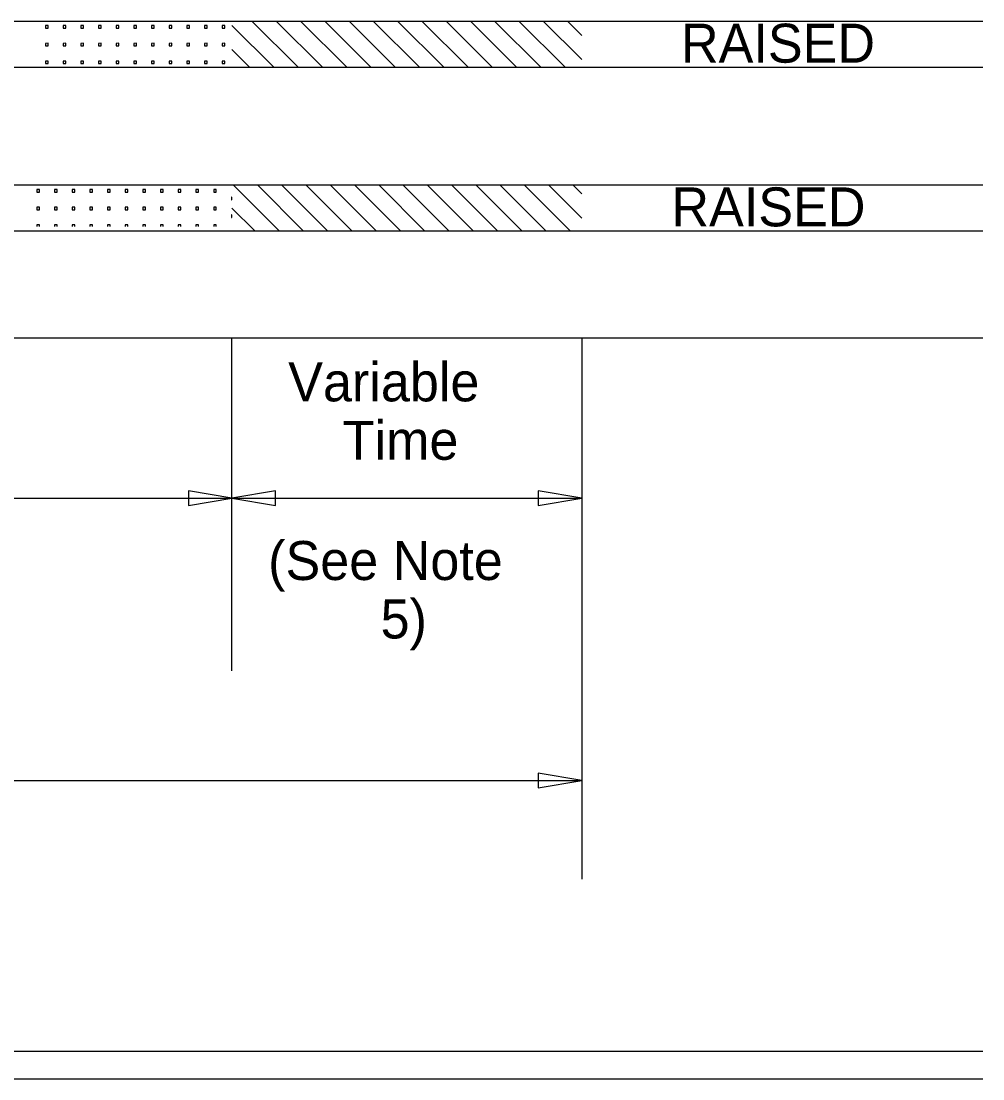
# Model space of a CAD drawing. Extents: x 15 to 764, y 7 to 487.
# Drawn here: x 670.2 to 756.6, y 29.1 to 124.1 of the extents above; entities that cross this region are included whole.
import ezdxf

# ---------------------------------------------------------------- set-up
doc = ezdxf.new("R2010")
doc.units = 0
for name, color, linetype in [('Default', 7, 'Continuous'), ('Dimension', 7, 'Continuous'), ('TextStructures', 7, 'Continuous')]:
    doc.layers.add(name, color=color, linetype=linetype)

msp = doc.modelspace()

# ---------------------------------------------------------------- linework, layer by layer
at = {"layer": 'Default'}
for p, q in [((462.687, 124.052), (756.61, 124.052)), ((706.225, 124.052), (710.375, 119.905)), ((708.406, 124.052), (712.555, 119.905)), ((710.586, 124.052), (714.736, 119.905)), ((712.766, 124.052), (716.916, 119.905)), ((714.947, 124.052), (719.097, 119.905)), ((717.127, 124.052), (720.584, 120.598)), ((719.308, 124.052), (720.584, 122.777)), ((462.687, 119.905), (756.61, 119.905)), ((462.687, 109.343), (756.61, 109.343)), ((708.887, 109.343), (713.014, 105.216)), ((711.066, 109.343), (715.194, 105.216)), ((713.246, 109.343), (717.374, 105.216)), ((715.426, 109.343), (719.553, 105.216)), ((717.606, 109.343), (720.584, 106.366)), ((719.786, 109.343), (720.584, 108.545)), ((462.687, 95.608), (756.61, 95.608)), ((689.177, 65.69), (689.177, 95.608)), ((720.584, 95.608), (720.584, 46.998)), ((624.556, 81.197), (689.177, 81.197)), ((689.177, 81.197), (720.584, 81.197)), ((495.877, 55.858), (720.584, 55.858))]:
    msp.add_line(p, q, dxfattribs=at)
for points in [[(672.656, 123.41), (672.656, 123.649), (672.417, 123.648), (672.417, 123.41), (672.656, 123.41)], [(672.656, 123.41), (672.656, 123.649), (672.417, 123.648), (672.417, 123.41), (672.656, 123.41)], [(674.242, 123.41), (674.242, 123.649), (674.003, 123.648), (674.003, 123.41), (674.242, 123.41)], [(674.242, 123.41), (674.242, 123.649), (674.003, 123.648), (674.003, 123.41), (674.242, 123.41)], [(675.832, 123.41), (675.832, 123.649), (675.593, 123.648), (675.593, 123.41), (675.832, 123.41)], [(675.832, 123.41), (675.832, 123.649), (675.593, 123.648), (675.593, 123.41), (675.832, 123.41)], [(677.418, 123.41), (677.418, 123.649), (677.179, 123.648), (677.179, 123.41), (677.418, 123.41)], [(677.418, 123.41), (677.418, 123.649), (677.179, 123.648), (677.179, 123.41), (677.418, 123.41)], [(679.008, 123.41), (679.008, 123.649), (678.769, 123.648), (678.769, 123.41), (679.008, 123.41)], [(679.008, 123.41), (679.008, 123.649), (678.769, 123.648), (678.769, 123.41), (679.008, 123.41)], [(680.594, 123.41), (680.594, 123.649), (680.355, 123.648), (680.355, 123.41), (680.594, 123.41)], [(680.594, 123.41), (680.594, 123.649), (680.355, 123.648), (680.355, 123.41), (680.594, 123.41)], [(682.184, 123.41), (682.184, 123.649), (681.945, 123.648), (681.945, 123.41), (682.184, 123.41)], [(682.184, 123.41), (682.184, 123.649), (681.945, 123.648), (681.945, 123.41), (682.184, 123.41)], [(683.77, 123.41), (683.77, 123.649), (683.532, 123.648), (683.532, 123.41), (683.77, 123.41)], [(683.77, 123.41), (683.77, 123.649), (683.532, 123.648), (683.532, 123.41), (683.77, 123.41)], [(685.36, 123.41), (685.36, 123.649), (685.121, 123.648), (685.121, 123.41), (685.36, 123.41)], [(685.36, 123.41), (685.36, 123.649), (685.121, 123.648), (685.121, 123.41), (685.36, 123.41)], [(686.947, 123.41), (686.947, 123.649), (686.708, 123.648), (686.708, 123.41), (686.947, 123.41)], [(686.947, 123.41), (686.947, 123.649), (686.708, 123.648), (686.708, 123.41), (686.947, 123.41)], [(688.536, 123.41), (688.536, 123.649), (688.297, 123.648), (688.297, 123.41), (688.536, 123.41)], [(688.536, 123.41), (688.536, 123.649), (688.297, 123.648), (688.297, 123.41), (688.536, 123.41)], [(689.177, 123.671), (692.943, 119.905)], [(690.973, 124.052), (695.121, 119.905)], [(693.153, 124.052), (697.301, 119.905)], [(695.33, 124.052), (699.48, 119.905)], [(697.508, 124.052), (701.658, 119.905)], [(699.687, 124.052), (703.835, 119.905)], [(701.867, 124.052), (706.015, 119.905)], [(704.045, 124.052), (708.195, 119.905)], [(672.656, 121.823), (672.656, 122.062), (672.417, 122.06), (672.417, 121.823), (672.656, 121.823)], [(672.656, 121.823), (672.656, 122.062), (672.417, 122.06), (672.417, 121.823), (672.656, 121.823)], [(674.242, 121.823), (674.242, 122.062), (674.003, 122.06), (674.003, 121.823), (674.242, 121.823)], [(674.242, 121.823), (674.242, 122.062), (674.003, 122.06), (674.003, 121.823), (674.242, 121.823)], [(675.832, 121.823), (675.832, 122.062), (675.593, 122.06), (675.593, 121.823), (675.832, 121.823)], [(675.832, 121.823), (675.832, 122.062), (675.593, 122.06), (675.593, 121.823), (675.832, 121.823)], [(677.418, 121.823), (677.418, 122.062), (677.179, 122.06), (677.179, 121.823), (677.418, 121.823)], [(677.418, 121.823), (677.418, 122.062), (677.179, 122.06), (677.179, 121.823), (677.418, 121.823)], [(679.008, 121.823), (679.008, 122.062), (678.769, 122.06), (678.769, 121.823), (679.008, 121.823)], [(679.008, 121.823), (679.008, 122.062), (678.769, 122.06), (678.769, 121.823), (679.008, 121.823)], [(680.594, 121.823), (680.594, 122.062), (680.355, 122.06), (680.355, 121.823), (680.594, 121.823)], [(680.594, 121.823), (680.594, 122.062), (680.355, 122.06), (680.355, 121.823), (680.594, 121.823)], [(682.184, 121.823), (682.184, 122.062), (681.945, 122.06), (681.945, 121.823), (682.184, 121.823)], [(682.184, 121.823), (682.184, 122.062), (681.945, 122.06), (681.945, 121.823), (682.184, 121.823)], [(683.77, 121.823), (683.77, 122.062), (683.532, 122.06), (683.532, 121.823), (683.77, 121.823)], [(683.77, 121.823), (683.77, 122.062), (683.532, 122.06), (683.532, 121.823), (683.77, 121.823)], [(685.36, 121.823), (685.36, 122.062), (685.121, 122.06), (685.121, 121.823), (685.36, 121.823)], [(685.36, 121.823), (685.36, 122.062), (685.121, 122.06), (685.121, 121.823), (685.36, 121.823)], [(686.947, 121.823), (686.947, 122.062), (686.708, 122.06), (686.708, 121.823), (686.947, 121.823)], [(686.947, 121.823), (686.947, 122.062), (686.708, 122.06), (686.708, 121.823), (686.947, 121.823)], [(688.536, 121.823), (688.536, 122.062), (688.297, 122.06), (688.297, 121.823), (688.536, 121.823)], [(688.536, 121.823), (688.536, 122.062), (688.297, 122.06), (688.297, 121.823), (688.536, 121.823)], [(689.177, 121.492), (690.764, 119.905)], [(672.656, 120.234), (672.656, 120.473), (672.417, 120.472), (672.417, 120.234), (672.656, 120.234)], [(672.656, 120.234), (672.656, 120.473), (672.417, 120.472), (672.417, 120.234), (672.656, 120.234)], [(674.242, 120.234), (674.242, 120.473), (674.003, 120.472), (674.003, 120.234), (674.242, 120.234)], [(674.242, 120.234), (674.242, 120.473), (674.003, 120.472), (674.003, 120.234), (674.242, 120.234)], [(675.832, 120.234), (675.832, 120.473), (675.593, 120.472), (675.593, 120.234), (675.832, 120.234)], [(675.832, 120.234), (675.832, 120.473), (675.593, 120.472), (675.593, 120.234), (675.832, 120.234)], [(677.418, 120.234), (677.418, 120.473), (677.179, 120.472), (677.179, 120.234), (677.418, 120.234)], [(677.418, 120.234), (677.418, 120.473), (677.179, 120.472), (677.179, 120.234), (677.418, 120.234)], [(679.008, 120.234), (679.008, 120.473), (678.769, 120.472), (678.769, 120.234), (679.008, 120.234)], [(679.008, 120.234), (679.008, 120.473), (678.769, 120.472), (678.769, 120.234), (679.008, 120.234)], [(680.594, 120.234), (680.594, 120.473), (680.355, 120.472), (680.355, 120.234), (680.594, 120.234)], [(680.594, 120.234), (680.594, 120.473), (680.355, 120.472), (680.355, 120.234), (680.594, 120.234)], [(682.184, 120.234), (682.184, 120.473), (681.945, 120.472), (681.945, 120.234), (682.184, 120.234)], [(682.184, 120.234), (682.184, 120.473), (681.945, 120.472), (681.945, 120.234), (682.184, 120.234)], [(683.77, 120.234), (683.77, 120.473), (683.532, 120.472), (683.532, 120.234), (683.77, 120.234)], [(683.77, 120.234), (683.77, 120.473), (683.532, 120.472), (683.532, 120.234), (683.77, 120.234)], [(685.36, 120.234), (685.36, 120.473), (685.121, 120.472), (685.121, 120.234), (685.36, 120.234)], [(685.36, 120.234), (685.36, 120.473), (685.121, 120.472), (685.121, 120.234), (685.36, 120.234)], [(686.947, 120.234), (686.947, 120.473), (686.708, 120.472), (686.708, 120.234), (686.947, 120.234)], [(686.947, 120.234), (686.947, 120.473), (686.708, 120.472), (686.708, 120.234), (686.947, 120.234)], [(688.536, 120.234), (688.536, 120.473), (688.297, 120.472), (688.297, 120.234), (688.536, 120.234)], [(688.536, 120.234), (688.536, 120.473), (688.297, 120.472), (688.297, 120.234), (688.536, 120.234)], [(689.277, 109.343), (693.404, 105.216)], [(691.457, 109.343), (695.582, 105.216)], [(693.636, 109.343), (697.761, 105.216)], [(695.814, 109.343), (699.939, 105.216)], [(697.991, 109.343), (702.119, 105.216)], [(700.171, 109.343), (704.298, 105.216)], [(702.351, 109.343), (706.476, 105.216)], [(704.527, 109.343), (708.655, 105.216)], [(706.707, 109.343), (710.834, 105.216)], [(671.889, 108.697), (671.889, 108.937), (671.652, 108.935), (671.652, 108.697), (671.889, 108.697)], [(671.889, 108.697), (671.889, 108.937), (671.652, 108.935), (671.652, 108.697), (671.889, 108.697)], [(673.476, 108.697), (673.476, 108.937), (673.24, 108.935), (673.24, 108.697), (673.476, 108.697)], [(673.476, 108.697), (673.476, 108.937), (673.24, 108.935), (673.24, 108.697), (673.476, 108.697)], [(675.065, 108.697), (675.065, 108.937), (674.828, 108.935), (674.828, 108.697), (675.065, 108.697)], [(675.065, 108.697), (675.065, 108.937), (674.828, 108.935), (674.828, 108.697), (675.065, 108.697)], [(676.653, 108.697), (676.653, 108.937), (676.416, 108.935), (676.416, 108.697), (676.653, 108.697)], [(676.653, 108.697), (676.653, 108.937), (676.416, 108.935), (676.416, 108.697), (676.653, 108.697)], [(678.241, 108.697), (678.241, 108.937), (678.005, 108.935), (678.005, 108.697), (678.241, 108.697)], [(678.241, 108.697), (678.241, 108.937), (678.005, 108.935), (678.005, 108.697), (678.241, 108.697)], [(679.829, 108.697), (679.829, 108.937), (679.592, 108.935), (679.592, 108.697), (679.829, 108.697)], [(679.829, 108.697), (679.829, 108.937), (679.592, 108.935), (679.592, 108.697), (679.829, 108.697)], [(681.417, 108.697), (681.417, 108.937), (681.181, 108.935), (681.181, 108.697), (681.417, 108.697)], [(681.417, 108.697), (681.417, 108.937), (681.181, 108.935), (681.181, 108.697), (681.417, 108.697)], [(683.005, 108.697), (683.005, 108.937), (682.768, 108.935), (682.768, 108.697), (683.005, 108.697)], [(683.005, 108.697), (683.005, 108.937), (682.768, 108.935), (682.768, 108.697), (683.005, 108.697)], [(684.594, 108.697), (684.594, 108.937), (684.357, 108.935), (684.357, 108.697), (684.594, 108.697)], [(684.594, 108.697), (684.594, 108.937), (684.357, 108.935), (684.357, 108.697), (684.594, 108.697)], [(686.181, 108.697), (686.181, 108.937), (685.944, 108.935), (685.944, 108.697), (686.181, 108.697)], [(686.181, 108.697), (686.181, 108.937), (685.944, 108.935), (685.944, 108.697), (686.181, 108.697)], [(687.77, 108.697), (687.77, 108.937), (687.533, 108.935), (687.533, 108.697), (687.77, 108.697)], [(687.77, 108.697), (687.77, 108.937), (687.533, 108.935), (687.533, 108.697), (687.77, 108.697)], [(689.177, 108.248), (689.119, 108.248)], [(689.119, 108.248), (689.119, 108.01)], [(689.177, 108.248), (689.119, 108.248)], [(689.119, 108.248), (689.119, 108.01)], [(689.119, 108.01), (689.177, 108.01)], [(689.119, 108.01), (689.177, 108.01)], [(671.889, 107.109), (671.889, 107.348), (671.652, 107.347), (671.652, 107.109), (671.889, 107.109)], [(671.889, 107.109), (671.889, 107.348), (671.652, 107.347), (671.652, 107.109), (671.889, 107.109)], [(673.476, 107.109), (673.476, 107.348), (673.24, 107.347), (673.24, 107.109), (673.476, 107.109)], [(673.476, 107.109), (673.476, 107.348), (673.24, 107.347), (673.24, 107.109), (673.476, 107.109)], [(675.065, 107.109), (675.065, 107.348), (674.828, 107.347), (674.828, 107.109), (675.065, 107.109)], [(675.065, 107.109), (675.065, 107.348), (674.828, 107.347), (674.828, 107.109), (675.065, 107.109)], [(676.653, 107.109), (676.653, 107.348), (676.416, 107.347), (676.416, 107.109), (676.653, 107.109)], [(676.653, 107.109), (676.653, 107.348), (676.416, 107.347), (676.416, 107.109), (676.653, 107.109)], [(678.241, 107.109), (678.241, 107.348), (678.005, 107.347), (678.005, 107.109), (678.241, 107.109)], [(678.241, 107.109), (678.241, 107.348), (678.005, 107.347), (678.005, 107.109), (678.241, 107.109)], [(679.829, 107.109), (679.829, 107.348), (679.592, 107.347), (679.592, 107.109), (679.829, 107.109)], [(679.829, 107.109), (679.829, 107.348), (679.592, 107.347), (679.592, 107.109), (679.829, 107.109)], [(681.417, 107.109), (681.417, 107.348), (681.181, 107.347), (681.181, 107.109), (681.417, 107.109)], [(681.417, 107.109), (681.417, 107.348), (681.181, 107.347), (681.181, 107.109), (681.417, 107.109)], [(683.005, 107.109), (683.005, 107.348), (682.768, 107.347), (682.768, 107.109), (683.005, 107.109)], [(683.005, 107.109), (683.005, 107.348), (682.768, 107.347), (682.768, 107.109), (683.005, 107.109)], [(684.594, 107.109), (684.594, 107.348), (684.357, 107.347), (684.357, 107.109), (684.594, 107.109)], [(684.594, 107.109), (684.594, 107.348), (684.357, 107.347), (684.357, 107.109), (684.594, 107.109)], [(686.181, 107.109), (686.181, 107.348), (685.944, 107.347), (685.944, 107.109), (686.181, 107.109)], [(686.181, 107.109), (686.181, 107.348), (685.944, 107.347), (685.944, 107.109), (686.181, 107.109)], [(687.77, 107.109), (687.77, 107.348), (687.533, 107.347), (687.533, 107.109), (687.77, 107.109)], [(687.77, 107.109), (687.77, 107.348), (687.533, 107.347), (687.533, 107.109), (687.77, 107.109)], [(689.177, 106.66), (689.119, 106.66)], [(689.119, 106.66), (689.119, 106.421)], [(689.177, 106.66), (689.119, 106.66)], [(689.119, 106.66), (689.119, 106.421)], [(689.119, 106.421), (689.177, 106.421)], [(689.119, 106.421), (689.177, 106.421)], [(689.177, 107.266), (691.224, 105.216)], [(671.889, 105.761), (671.652, 105.758)], [(671.652, 105.758), (671.652, 105.595)], [(671.889, 105.595), (671.889, 105.761)], [(673.476, 105.761), (673.24, 105.758)], [(673.24, 105.758), (673.24, 105.595)], [(673.476, 105.595), (673.476, 105.761)], [(675.065, 105.761), (674.828, 105.758)], [(674.828, 105.758), (674.828, 105.595)], [(675.065, 105.595), (675.065, 105.761)], [(676.653, 105.761), (676.416, 105.758)], [(676.416, 105.758), (676.416, 105.595)], [(676.653, 105.595), (676.653, 105.761)], [(678.241, 105.761), (678.005, 105.758)], [(678.005, 105.758), (678.005, 105.595)], [(678.241, 105.595), (678.241, 105.761)], [(679.829, 105.761), (679.592, 105.758)], [(679.592, 105.758), (679.592, 105.595)], [(679.829, 105.595), (679.829, 105.761)], [(681.417, 105.761), (681.181, 105.758)], [(681.181, 105.758), (681.181, 105.595)], [(681.417, 105.595), (681.417, 105.761)], [(683.005, 105.761), (682.768, 105.758)], [(682.768, 105.758), (682.768, 105.595)], [(683.005, 105.595), (683.005, 105.761)], [(684.594, 105.761), (684.357, 105.758)], [(684.357, 105.758), (684.357, 105.595)], [(684.594, 105.595), (684.594, 105.761)], [(686.181, 105.761), (685.944, 105.758)], [(685.944, 105.758), (685.944, 105.595)], [(686.181, 105.595), (686.181, 105.761)], [(687.77, 105.761), (687.533, 105.758)], [(687.533, 105.758), (687.533, 105.595)], [(687.77, 105.595), (687.77, 105.761)]]:
    msp.add_lwpolyline(points, dxfattribs=at)
at = {"layer": 'Dimension'}
for points in [[(689.177, 81.197), (685.272, 81.859), (685.272, 80.536)], [(689.177, 81.197), (693.082, 80.536), (693.082, 81.859)], [(720.584, 81.197), (716.679, 81.859), (716.679, 80.536)], [(720.584, 55.858), (716.679, 56.52), (716.679, 55.197)]]:
    msp.add_lwpolyline(points, close=True, dxfattribs=at)
at = {"layer": 'TextStructures'}
for p, q in [((462.687, 105.216), (756.61, 105.216)), ((581.413, 31.553), (756.61, 31.553)), ((581.413, 29.053), (756.61, 29.053))]:
    msp.add_line(p, q, dxfattribs=at)

# ---------------------------------------------------------------- texts
for p in [(729.501, 120.324), (728.643, 105.62)]:
    msp.add_text('RAISED', height=3.5, rotation=0.00072, dxfattribs=at).set_placement(p)
for s, p in [('Variable', (694.226, 89.904)), (' Time', (697.814, 84.654)), ('(See Note', (692.424, 73.857)), ('5)', (702.523, 68.607))]:
    msp.add_text(s, height=3.5, dxfattribs=at).set_placement(p)

doc.saveas('drawing.dxf')
